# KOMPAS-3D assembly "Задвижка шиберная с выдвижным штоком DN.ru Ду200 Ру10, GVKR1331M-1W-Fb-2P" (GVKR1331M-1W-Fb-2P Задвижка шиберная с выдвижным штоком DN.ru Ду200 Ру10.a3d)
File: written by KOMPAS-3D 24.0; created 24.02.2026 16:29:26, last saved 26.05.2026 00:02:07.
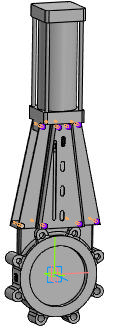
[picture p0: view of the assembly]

Document properties: Автор: R2D2; Полное имя файла: E:\Работа\Зайцев\GVKR1331M-1W-Fb-2P Задвижка шиберная с выдвижным штоком DN.ru Ду50-300 Ру16-10-6 с пневмоприводом\исходные материалы\DN200\GVKR1331M-1W-Fb-2P Задвижка шиберная с выдвижным штоком DN.ru Ду200 Ру10.a3d

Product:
- Component [detail]: Затвор дисковый DN.ru Ду Ру  | qty 1  | pos. 1  | Масса: 18.2; Раздел спецификации: Прочие изделия; Примечание: D050-23732; Автор: R2D2; source file: Задвижка шиберная РЕЗЬБОВОЙ DN.ru Ду Ру.m3d
- Component [detail]: Пневмоцилиндр  | qty 1  | pos. 2  | Масса: 44.90287; Автор: R2D2; source file: Пневмоцилиндр.m3d
- Component [standard]: Hexagon head screw ISO 4017 - М10 x 25  | qty 8  | pos. 5  | Масса: 0.026096; Раздел спецификации: Стандартные изделия; Рассекать на разрезах: no
- Component [detail]: лист  | qty 2  | pos. 3  | Масса: 2.594022; Раздел спецификации: Прочие изделия; Примечание: D040-08800; Автор: R2D2; source file: лист.m3d
- Component [detail]: шибер  | qty 1  | pos. 4  | Масса: 2.843453; Раздел спецификации: Прочие изделия; Примечание: D040-08800; Автор: R2D2; source file: шибер.m3d
- Component [standard]: Hexagon head screw ISO 4017 - М8 x 16  | qty 8  | Масса: 0.012085; Раздел спецификации: Стандартные изделия; Рассекать на разрезах: no
- Part/product: Задвижка шиберная с выдвижным штоком DN.ru Ду200 Ру10  | designation GVKR1331M-1W-Fb-2P
    Масса: 31
    Раздел спецификации: Прочие изделия
    Примечание: D040-08797

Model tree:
1. Точка:1  (with: Ребро.Отверстие в листовом теле:2)
     X = -60.8804; Y = 172.5; Z = 59
2. Точка:2  (with: Ребро.Отверстие в листовом теле:3)
     X = 60.8804; Y = 172.5; Z = 59
3. Точка:3  (with: Ребро.Отверстие в листовом теле:4)
     X = 130.651; Y = 172.5; Z = 34
4. Точка:4  (with: Ребро.Отверстие в листовом теле:5)
     X = -62.4332; Y = 493.5; Z = 34
5. Точка:5  (with: Ребро.Отверстие в листовом теле:6)
     X = -16.5828; Y = 493.5; Z = 59
6. Точка:6  (with: Ребро.Отверстие в листовом теле:7)
     X = 16.5828; Y = 493.5; Z = 59
7. Точка:7  (with: Ребро.Отверстие в листовом теле:8)
     X = 62.4332; Y = 493.5; Z = 34
8. Массив по точкам:1
9. Экземпляр ( 6 )
10. Экземпляр ( 4 )
11. Экземпляр ( 1 )
12. Экземпляр ( 7 )
13. Экземпляр ( 3 )
14. Экземпляр ( 5 )
15. Экземпляр ( 2 )
16. Контекстная связь:1  (with: Эскиз:7, Грань.Элемент выдавливания:6, Ребро.Элемент выдавливания:6, Ребро.Элемент выдавливания:12, Контекстная связь (лист (1)):1)
17. Контекстная связь:2  (with: Эскиз:6, Грань.Элемент выдавливания:15, Ребро.Элемент выдавливания:15, Контекстная связь (лист (1)):2)
18. Контекстная связь:3  (with: Эскиз:5, Грань.Элемент выдавливания:1, Вершина.Элемент выдавливания:15, Контекстная связь (шибер):3, Грань.Элемент выдавливания:8, Грань.Линейчатая обечайка:1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)
     Ориентация = 2; Ориентация = 2; Ориентация = 2; Ориентация = 2; Ориентация = 2; Ориентация = 2; Ориентация = 2; Ориентация = 2; Ориентация = 2

Expressions: D050-23732; D040-08800
Referenced files in E:\Работа\Зайцев\GVKR1331M-1W-Fb-2P Задвижка шиберная с выдвижным штоком DN.ru Ду50-300 Ру16-10-6 с пневмоприводом\исходные материалы\DN200\: Задвижка шиберная РЕЗЬБОВОЙ DN.ru Ду Ру.m3d, Пневмоцилиндр.m3d, лист.m3d, шибер.m3d
Referenced files in C:\Program Files\ASCON\KOMPAS-3D v24\Libs\PolynomLib\DATA\vault\Methods\Kompas\3D\: PLib_Bolt_1_ISO_1100.m3d
Referenced files in E:\Работа\Зайцев\GVKR1331E-1W-Fb-2P Задвижка шиберная DN.ru Ду50-300 Ру16-10-6\исходные материалы\DN80\: лист.m3d
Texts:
  Hexagon head screw
  BOSimple***PART:f114febc-ab7b-6638-bb5e-15f0e2e47160***SHORTLOC:A259_7B16EF33AB1642D2[16;1,5;25;10;-;Undefined]
  BOSimple***PART:17775d1c-e7de-f283-40f0-d40789f7f59e***SHORTLOC:A259_7B16EF33AB1642D2[13;1,25;16;8;-;Undefined]
  Программные изделия  и базы данных
  GVKR1331M-1W-Fb-2P
  Hexagon head screw ISO 4017 - М10 x 25 (1)
  hole1
  hole2
  лист (1)
  лист (2)
  Hexagon head screw ISO 4017 - М8 x 16 (1)
  Hexagon head screw ISO 4017 - М8 x 16 (2)
  Hexagon head screw ISO 4017 - М8 x 16 (3)
  Hexagon head screw ISO 4017 - М8 x 16 (4)
  Hexagon head screw ISO 4017 - М8 x 16 (5)
  Hexagon head screw ISO 4017 - М8 x 16 (6)
  Hexagon head screw ISO 4017 - М8 x 16 (7)
  Hexagon head screw ISO 4017 - М8 x 16 (8)
  Ось Y.Начало координат
  Плоскость ZY.Начало координат
  Плоскость ZX.Начало координат
  Плоскость XY.Начало координат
